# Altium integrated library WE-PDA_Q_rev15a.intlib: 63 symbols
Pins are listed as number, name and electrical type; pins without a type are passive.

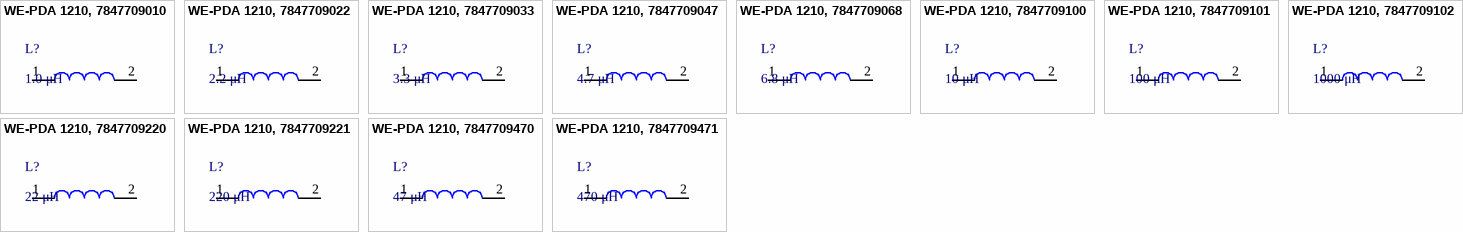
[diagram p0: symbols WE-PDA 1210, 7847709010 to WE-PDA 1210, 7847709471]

## WE-PDA 1210, 7847709010
designator L?, comment 1.0 μH
WE-PDA SMD Shielded Power InductorInductance = 1.0 μH; partNo: 7847709010; Manufacturer: Wurth Elektronik
footprint WE-PDA_1210
pins: 1, 2

## WE-PDA 1210, 7847709022
designator L?, comment 2.2 μH
WE-PDA SMD Shielded Power InductorInductance = 2.2 μH; partNo: 7847709022; Manufacturer: Wurth Elektronik
footprint WE-PDA_1210
pins: 1, 2

## WE-PDA 1210, 7847709033
designator L?, comment 3.3 μH
WE-PDA SMD Shielded Power InductorInductance = 3.3 μH; partNo: 7847709033; Manufacturer: Wurth Elektronik
footprint WE-PDA_1210
pins: 1, 2

## WE-PDA 1210, 7847709047
designator L?, comment 4.7 μH
WE-PDA SMD Shielded Power InductorInductance = 4.7 μH; partNo: 7847709047; Manufacturer: Wurth Elektronik
footprint WE-PDA_1210
pins: 1, 2

## WE-PDA 1210, 7847709068
designator L?, comment 6.8 μH
WE-PDA SMD Shielded Power InductorInductance = 6.8 μH; partNo: 7847709068; Manufacturer: Wurth Elektronik
footprint WE-PDA_1210
pins: 1, 2

## WE-PDA 1210, 7847709100
designator L?, comment 10 μH
WE-PDA SMD Shielded Power InductorInductance = 10 μH; partNo: 7847709100; Manufacturer: Wurth Elektronik
footprint WE-PDA_1210
pins: 1, 2

## WE-PDA 1210, 7847709101
designator L?, comment 100 μH
WE-PDA SMD Shielded Power InductorInductance = 100 μH; partNo: 7847709101; Manufacturer: Wurth Elektronik
footprint WE-PDA_1210
pins: 1, 2

## WE-PDA 1210, 7847709102
designator L?, comment 1000 μH
WE-PDA SMD Shielded Power InductorInductance = 1000 μH; partNo: 7847709102; Manufacturer: Wurth Elektronik
footprint WE-PDA_1210
pins: 1, 2

## WE-PDA 1210, 7847709220
designator L?, comment 22 μH
WE-PDA SMD Shielded Power InductorInductance = 22 μH; partNo: 7847709220; Manufacturer: Wurth Elektronik
footprint WE-PDA_1210
pins: 1, 2

## WE-PDA 1210, 7847709221
designator L?, comment 220 μH
WE-PDA SMD Shielded Power InductorInductance = 220 μH; partNo: 7847709221; Manufacturer: Wurth Elektronik
footprint WE-PDA_1210
pins: 1, 2

## WE-PDA 1210, 7847709470
designator L?, comment 47 μH
WE-PDA SMD Shielded Power InductorInductance = 47 μH; partNo: 7847709470; Manufacturer: Wurth Elektronik
footprint WE-PDA_1210
pins: 1, 2

## WE-PDA 1210, 7847709471
designator L?, comment 470 μH
WE-PDA SMD Shielded Power InductorInductance = 470 μH; partNo: 7847709471; Manufacturer: Wurth Elektronik
footprint WE-PDA_1210
pins: 1, 2


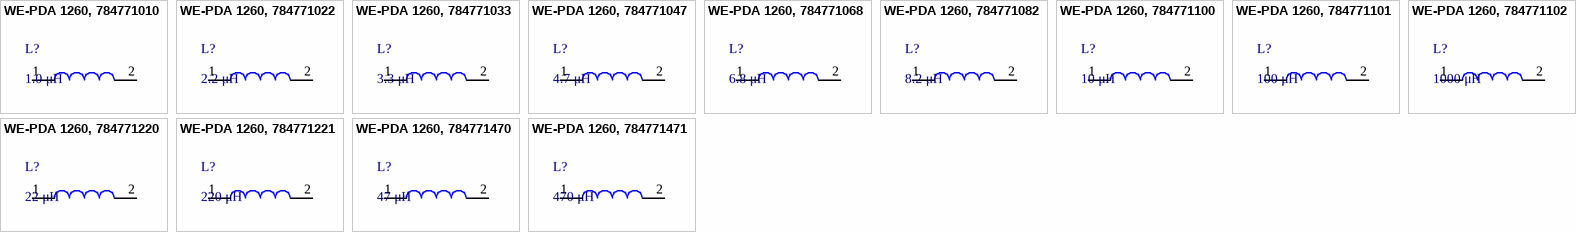
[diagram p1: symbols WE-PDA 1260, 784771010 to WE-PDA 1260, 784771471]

## WE-PDA 1260, 784771010
designator L?, comment 1.0 μH
WE-PDA SMD Shielded Power InductorInductance = 1.0 μH; partNo: 784771010; Manufacturer: Wurth Elektronik
footprint WE-PDA_1260
pins: 1, 2

## WE-PDA 1260, 784771022
designator L?, comment 2.2 μH
WE-PDA SMD Shielded Power InductorInductance = 2.2 μH; partNo: 784771022; Manufacturer: Wurth Elektronik
footprint WE-PDA_1260
pins: 1, 2

## WE-PDA 1260, 784771033
designator L?, comment 3.3 μH
WE-PDA SMD Shielded Power InductorInductance = 3.3 μH; partNo: 784771033; Manufacturer: Wurth Elektronik
footprint WE-PDA_1260
pins: 1, 2

## WE-PDA 1260, 784771047
designator L?, comment 4.7 μH
WE-PDA SMD Shielded Power InductorInductance = 4.7 μH; partNo: 784771047; Manufacturer: Wurth Elektronik
footprint WE-PDA_1260
pins: 1, 2

## WE-PDA 1260, 784771068
designator L?, comment 6.8 μH
WE-PDA SMD Shielded Power InductorInductance = 6.8 μH; partNo: 784771068; Manufacturer: Wurth Elektronik
footprint WE-PDA_1260
pins: 1, 2

## WE-PDA 1260, 784771082
designator L?, comment 8.2 μH
WE-PDA SMD Shielded Power InductorInductance = 8.2 μH; partNo: 784771082; Manufacturer: Wurth Elektronik
footprint WE-PDA_1260
pins: 1, 2

## WE-PDA 1260, 784771100
designator L?, comment 10 μH
WE-PDA SMD Shielded Power InductorInductance = 10 μH; partNo: 784771100; Manufacturer: Wurth Elektronik
footprint WE-PDA_1260
pins: 1, 2

## WE-PDA 1260, 784771101
designator L?, comment 100 μH
WE-PDA SMD Shielded Power InductorInductance = 100 μH; partNo: 784771101; Manufacturer: Wurth Elektronik
footprint WE-PDA_1260
pins: 1, 2

## WE-PDA 1260, 784771102
designator L?, comment 1000 μH
WE-PDA SMD Shielded Power InductorInductance = 1000 μH; partNo: 784771102; Manufacturer: Wurth Elektronik
footprint WE-PDA_1260
pins: 1, 2

## WE-PDA 1260, 784771220
designator L?, comment 22 μH
WE-PDA SMD Shielded Power InductorInductance = 22 μH; partNo: 784771220; Manufacturer: Wurth Elektronik
footprint WE-PDA_1260
pins: 1, 2

## WE-PDA 1260, 784771221
designator L?, comment 220 μH
WE-PDA SMD Shielded Power InductorInductance = 220 μH; partNo: 784771221; Manufacturer: Wurth Elektronik
footprint WE-PDA_1260
pins: 1, 2

## WE-PDA 1260, 784771470
designator L?, comment 47 μH
WE-PDA SMD Shielded Power InductorInductance = 47 μH; partNo: 784771470; Manufacturer: Wurth Elektronik
footprint WE-PDA_1260
pins: 1, 2

## WE-PDA 1260, 784771471
designator L?, comment 470 μH
WE-PDA SMD Shielded Power InductorInductance = 470 μH; partNo: 784771471; Manufacturer: Wurth Elektronik
footprint WE-PDA_1260
pins: 1, 2


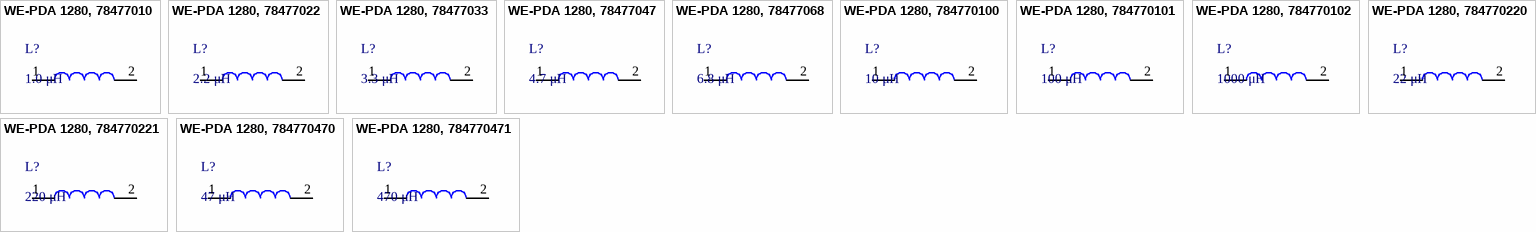
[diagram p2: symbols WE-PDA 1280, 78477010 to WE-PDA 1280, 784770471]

## WE-PDA 1280, 78477010
designator L?, comment 1.0 μH
WE-PDA SMD Shielded Power Inductor ,Inductance = 1.0 μH; partNo: 78477010; Manufacturer: Wurth Elektronik
footprint WE-PDA_1280
pins: 1, 2

## WE-PDA 1280, 78477022
designator L?, comment 2.2 μH
WE-PDA SMD Shielded Power InductorInductance = 2.2 μH; partNo: 78477022; Manufacturer: Wurth Elektronik
footprint WE-PDA_1280
pins: 1, 2

## WE-PDA 1280, 78477033
designator L?, comment 3.3 μH
WE-PDA SMD Shielded Power InductorInductance = 3.3 μH; partNo: 78477033; Manufacturer: Wurth Elektronik
footprint WE-PDA_1280
pins: 1, 2

## WE-PDA 1280, 78477047
designator L?, comment 4.7 μH
WE-PDA SMD Shielded Power InductorInductance = 4.7 μH; partNo: 78477047; Manufacturer: Wurth Elektronik
footprint WE-PDA_1280
pins: 1, 2

## WE-PDA 1280, 78477068
designator L?, comment 6.8 μH
WE-PDA SMD Shielded Power InductorInductance = 6.8 μH; partNo: 78477068; Manufacturer: Wurth Elektronik
footprint WE-PDA_1280
pins: 1, 2

## WE-PDA 1280, 784770100
designator L?, comment 10 μH
WE-PDA SMD Shielded Power InductorInductance = 10 μH; partNo: 784770100; Manufacturer: Wurth Elektronik
footprint WE-PDA_1280
pins: 1, 2

## WE-PDA 1280, 784770101
designator L?, comment 100 μH
WE-PDA SMD Shielded Power InductorInductance = 100 μH; partNo: 784770101; Manufacturer: Wurth Elektronik
footprint WE-PDA_1280
pins: 1, 2

## WE-PDA 1280, 784770102
designator L?, comment 1000 μH
WE-PDA SMD Shielded Power InductorInductance = 1000 μH; partNo: 784770102; Manufacturer: Wurth Elektronik
footprint WE-PDA_1280
pins: 1, 2

## WE-PDA 1280, 784770220
designator L?, comment 22 μH
WE-PDA SMD Shielded Power InductorInductance = 22 μH; partNo: 784770220; Manufacturer: Wurth Elektronik
footprint WE-PDA_1280
pins: 1, 2

## WE-PDA 1280, 784770221
designator L?, comment 220 μH
WE-PDA SMD Shielded Power InductorInductance = 220 μH; partNo: 784770221; Manufacturer: Wurth Elektronik
footprint WE-PDA_1280
pins: 1, 2

## WE-PDA 1280, 784770470
designator L?, comment 47 μH
WE-PDA SMD Shielded Power InductorInductance = 47 μH; partNo: 784770470; Manufacturer: Wurth Elektronik
footprint WE-PDA_1280
pins: 1, 2

## WE-PDA 1280, 784770471
designator L?, comment 470 μH
WE-PDA SMD Shielded Power InductorInductance = 470 μH; partNo: 784770471; Manufacturer: Wurth Elektronik
footprint WE-PDA_1280
pins: 1, 2


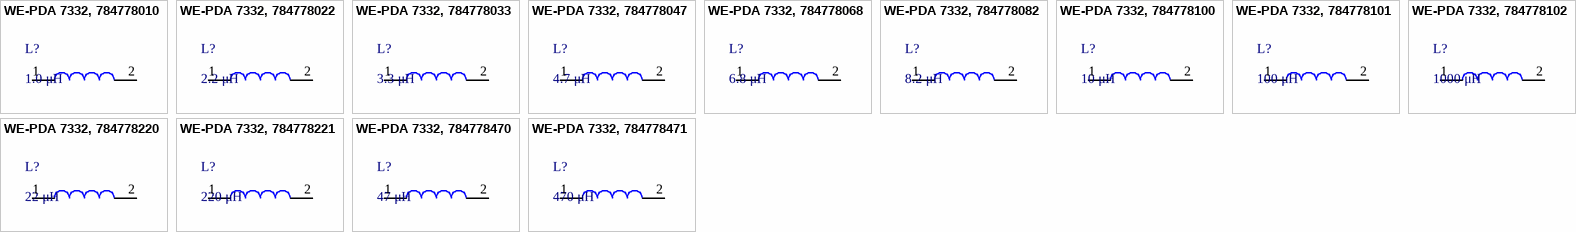
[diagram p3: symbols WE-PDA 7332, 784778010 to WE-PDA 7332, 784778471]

## WE-PDA 7332, 784778010
designator L?, comment 1.0 μH
WE-PDA SMD Shielded Power InductorInductance = 1.0 μH; partNo: 784778010; Manufacturer: Wurth Elektronik
footprint WE-PDA_7332
pins: 1, 2

## WE-PDA 7332, 784778022
designator L?, comment 2.2 μH
WE-PDA SMD Shielded Power InductorInductance = 2.2 μH; partNo: 784778022; Manufacturer: Wurth Elektronik
footprint WE-PDA_7332
pins: 1, 2

## WE-PDA 7332, 784778033
designator L?, comment 3.3 μH
WE-PDA SMD Shielded Power InductorInductance = 3.3 μH; partNo: 784778033; Manufacturer: Wurth Elektronik
footprint WE-PDA_7332
pins: 1, 2

## WE-PDA 7332, 784778047
designator L?, comment 4.7 μH
WE-PDA SMD Shielded Power InductorInductance = 4.7 μH; partNo: 784778047; Manufacturer: Wurth Elektronik
footprint WE-PDA_7332
pins: 1, 2

## WE-PDA 7332, 784778068
designator L?, comment 6.8 μH
WE-PDA SMD Shielded Power InductorInductance = 6.8 μH; partNo: 784778068; Manufacturer: Wurth Elektronik
footprint WE-PDA_7332
pins: 1, 2

## WE-PDA 7332, 784778082
designator L?, comment 8.2 μH
WE-PDA SMD Shielded Power InductorInductance = 8.2 μH; partNo: 784778082; Manufacturer: Wurth Elektronik
footprint WE-PDA_7332
pins: 1, 2

## WE-PDA 7332, 784778100
designator L?, comment 10 μH
WE-PDA SMD Shielded Power InductorInductance = 10 μH; partNo: 784778100; Manufacturer: Wurth Elektronik
footprint WE-PDA_7332
pins: 1, 2

## WE-PDA 7332, 784778101
designator L?, comment 100 μH
WE-PDA SMD Shielded Power InductorInductance = 100 μH; partNo: 784778101; Manufacturer: Wurth Elektronik
footprint WE-PDA_7332
pins: 1, 2

## WE-PDA 7332, 784778102
designator L?, comment 1000 μH
WE-PDA SMD Shielded Power InductorInductance = 1000 μH; partNo: 784778102; Manufacturer: Wurth Elektronik
footprint WE-PDA_7332
pins: 1, 2

## WE-PDA 7332, 784778220
designator L?, comment 22 μH
WE-PDA SMD Shielded Power InductorInductance = 22 μH; partNo: 784778220; Manufacturer: Wurth Elektronik
footprint WE-PDA_7332
pins: 1, 2

## WE-PDA 7332, 784778221
designator L?, comment 220 μH
WE-PDA SMD Shielded Power InductorInductance = 220 μH; partNo: 784778221; Manufacturer: Wurth Elektronik
footprint WE-PDA_7332
pins: 1, 2

## WE-PDA 7332, 784778470
designator L?, comment 47 μH
WE-PDA SMD Shielded Power InductorInductance = 47 μH; partNo: 784778470; Manufacturer: Wurth Elektronik
footprint WE-PDA_7332
pins: 1, 2

## WE-PDA 7332, 784778471
designator L?, comment 470 μH
WE-PDA SMD Shielded Power InductorInductance = 470 μH; partNo: 784778471; Manufacturer: Wurth Elektronik
footprint WE-PDA_7332
pins: 1, 2


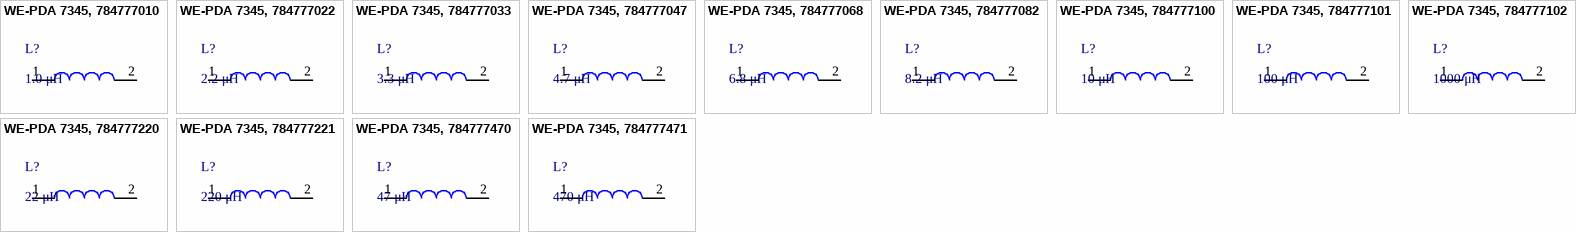
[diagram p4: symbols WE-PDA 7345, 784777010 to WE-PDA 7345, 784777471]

## WE-PDA 7345, 784777010
designator L?, comment 1.0 μH
WE-PDA SMD Shielded Power InductorInductance = 1.0 μH; partNo: 784777010; Manufacturer: Wurth Elektronik
footprint WE-PDA_7345
pins: 1, 2

## WE-PDA 7345, 784777022
designator L?, comment 2.2 μH
WE-PDA SMD Shielded Power InductorInductance = 2.2 μH; partNo: 784777022; Manufacturer: Wurth Elektronik
footprint WE-PDA_7345
pins: 1, 2

## WE-PDA 7345, 784777033
designator L?, comment 3.3 μH
WE-PDA SMD Shielded Power InductorInductance = 3.3 μH; partNo: 784777033; Manufacturer: Wurth Elektronik
footprint WE-PDA_7345
pins: 1, 2

## WE-PDA 7345, 784777047
designator L?, comment 4.7 μH
WE-PDA SMD Shielded Power InductorInductance = 4.7 μH; partNo: 784777047; Manufacturer: Wurth Elektronik
footprint WE-PDA_7345
pins: 1, 2

## WE-PDA 7345, 784777068
designator L?, comment 6.8 μH
WE-PDA SMD Shielded Power InductorInductance = 6.8 μH; partNo: 784777068; Manufacturer: Wurth Elektronik
footprint WE-PDA_7345
pins: 1, 2

## WE-PDA 7345, 784777082
designator L?, comment 8.2 μH
WE-PDA SMD Shielded Power InductorInductance = 8.2 μH; partNo: 784777082; Manufacturer: Wurth Elektronik
footprint WE-PDA_7345
pins: 1, 2

## WE-PDA 7345, 784777100
designator L?, comment 10 μH
WE-PDA SMD Shielded Power InductorInductance = 10 μH; partNo: 784777100; Manufacturer: Wurth Elektronik
footprint WE-PDA_7345
pins: 1, 2

## WE-PDA 7345, 784777101
designator L?, comment 100 μH
WE-PDA SMD Shielded Power InductorInductance = 100 μH; partNo: 784777101; Manufacturer: Wurth Elektronik
footprint WE-PDA_7345
pins: 1, 2

## WE-PDA 7345, 784777102
designator L?, comment 1000 μH
WE-PDA SMD Shielded Power InductorInductance = 1000 μH; partNo: 784777102; Manufacturer: Wurth Elektronik
footprint WE-PDA_7345
pins: 1, 2

## WE-PDA 7345, 784777220
designator L?, comment 22 μH
WE-PDA SMD Shielded Power InductorInductance = 22 μH; partNo: 784777220; Manufacturer: Wurth Elektronik
footprint WE-PDA_7345
pins: 1, 2

## WE-PDA 7345, 784777221
designator L?, comment 220 μH
WE-PDA SMD Shielded Power InductorInductance = 220 μH; partNo: 784777221; Manufacturer: Wurth Elektronik
footprint WE-PDA_7345
pins: 1, 2

## WE-PDA 7345, 784777470
designator L?, comment 47 μH
WE-PDA SMD Shielded Power InductorInductance = 47 μH; partNo: 784777470; Manufacturer: Wurth Elektronik
footprint WE-PDA_7345
pins: 1, 2

## WE-PDA 7345, 784777471
designator L?, comment 470 μH
WE-PDA SMD Shielded Power InductorInductance = 470 μH; partNo: 784777471; Manufacturer: Wurth Elektronik
footprint WE-PDA_7345
pins: 1, 2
